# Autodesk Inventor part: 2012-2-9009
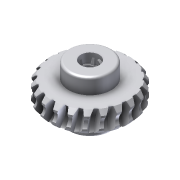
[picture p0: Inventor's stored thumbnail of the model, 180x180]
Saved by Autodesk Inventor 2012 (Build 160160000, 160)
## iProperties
Created: 2011-12
Part Number: 2012-2-9009
Material: Acetal Resin, White
Document SubType Name: Modeling
Designer: Admin
Categories: <?xml version="1.0" encoding="UTF-16"?> <MemberInstance><Categories><FamilyTemplate><FamilyTemplateParameter ValueType="xs:double" Id="1" ObjectReferenceKey="da
Density: 1.42 g/cm^3
Mass: 13.2974 g
Surface Area: 48.9318 cm^2
Volume: 9.36433 cm^3
Description: Worm Gear
CustomPartVersion: 1
Author: Admin
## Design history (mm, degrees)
body "Solid1"
node "Tooth Plane"
sketch "Base Body Sketch"
  geometry: L1 (0, -6.86)-(0, 6.86) reference; L2 (0, 4.409)-(16.217, 4.409); L3 (16.217, 4.409)-(17.69, 2.692); L4 (-4.98, 0)-(29.88, 0) reference; L5 (17.69, 2.692)-(17.69, -2.692); L6 (0, -4.409)-(16.217, -4.409); L7 (0, 4.409)-(0, -4.409); L8 (16.217, -4.409)-(17.69, -2.692); C1 r 3.01 at (20, 0)
  constraints: 14 end point, 3 symmetric about line, 2 perpendicular, 2 point on line, 1 centre point, 1 collinear
  dimensions: "d50" = 49.3717 deg angle of L3 L2 (= da_fi); "d87" = 35.38 diameter of L5 L1 (= da_dae); "d89" = 6.02 diameter of C1 (= 2 x da_aw - da_da); "d92" = 8.819 distance of L2.start L6.start (= da_b); "d93" = 20 distance from line of C1.centre L7 (= da_aw)
revolve "Base Body" stored, may be unused: angle "d35" = 90 deg
revolve "Base Body2" stored, may be unused: angle "d90" = 90 deg
workplane "Work Plane13"
revolve "Tooth" stored, may be unused: angle "d43" = 90 deg
pattern_circular "Tooth Pattern" dims angle "d46" = 360 deg
workplane "Work Plane14"
workplane "Work Plane15"
sketch "Sketch9"
  geometry: C1 r 9 at (0, 0); C2 r 4 at (0, 0); 1 further point
  constraints: 2 centre point, 2 coincident
  dimensions: "ShoulderOD" = 18 diameter of C1 (computed from d93); "ShaftOD" = 8 diameter of C2
extrude "Extrusion1" join sketch "Sketch9" stored distance "d96" = 22; taper "d97" = 0 deg
fillet "Fillet1" dims "d101" = 1
node "Shaft" dims "d120" = 10
feature "Sculpt2"
sketch "Tooth Sketch"
  geometry: L1 (10, 2.703)-(10, -2.703) reference; L2 (-11.596, 0)-(-0.424, 0) reference; L3 (-10, 1.931)-(-10, -1.931); L4 (-10, -1.931)-(-7.27, -1.931); L5 (-7.27, -1.931)-(-3.91, -0.708); L6 (-3.91, -0.708)-(-3.91, 0); L7 (-3.91, 0.708)-(-7.27, 1.931); L8 (-7.27, 1.931)-(-10, 1.931); L9 (-3.91, 0.708)-(-3.91, 0); L10 (-5.59, 0)-(-5.59, -1.319)
  constraints: 16 end point, 4 perpendicular, 3 equal length, 2 point on line, 1 midpoint, 1 parallel, 1 vertical
  dimensions: "d38" = 20 distance between parallel lines of L1 L3 (= da_aw); "d39" = 20 deg angle of L7 L8 (= da_alfat); "d40" = 2.73 distance of L7.end L3.start (= 0.5 x da_df1); "d41" = 4.41 distance between parallel lines of L3 L10 (= 0.5 x da_d1); "d42" = 1.31947 distance of L10.start L10.end (= 0.3 x da_px)
sketch "Sketch8"
  geometry: C1 r 16.217 at (0, 0) reference; C2 r 15.4 at (0, 0)
  constraints: 1 centre point, 1 coincident
  dimensions: "d77" = 30.8 diameter of C2 (= da_dw)
body "Srf1"
feature "Solid1::Shaft"
tag "TaggingFeature2"
feature "Pitch Diameter" dims "d78" = 8.819 (= da_b), "d79" = 0
body "Srf3"
other parameters: "da_aw" = 20 [user parameter; used in 5 equation terms], "da_fi" = 49.3717 deg [user parameter; used in 1 equation term], "da_b" = 8.819 [user parameter; used in 2 equation terms], "da_df" = 27.82 [user parameter], "da_da" = 33.98 [user parameter; used in 1 equation term], "da_beta" = 1.57417 [user parameter; used in 1 equation term], "da_alfat" = 20 deg [user parameter; used in 1 equation term], "da_df1" = 5.46 [user parameter; used in 1 equation term], "da_da1" = 11.62 [user parameter], "da_d1" = 8.82 [user parameter; used in 1 equation term], "da_px" = 4.39823 [user parameter; used in 1 equation term], "d37" = 1.57417 (computed from da_rightdir, da_beta), "d69" = 0, "d73" = 0, "d75" = 1.428 (computed from da_z), "da_dw" = 30.8 [user parameter; used in 1 equation term], "d80" = 0, "d81" = 0, "d82" = 0, "d83" = 1.428 (computed from da_z), "d84" = 0, "d85" = 180 deg, "da_dae" = 35.38 [user parameter; used in 1 equation term]
